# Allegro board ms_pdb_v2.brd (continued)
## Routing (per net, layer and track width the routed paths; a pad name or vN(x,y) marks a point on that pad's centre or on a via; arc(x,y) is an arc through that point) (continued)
T6_BLAD1_EN: length 112.2
  IN1 w0.127: J12.S3 83.46,235.78 v2(83.46,237.05) 83.46,239.82 84.26,240.62 84.26,241.45 83.46,242.25 83.46,245.37 64.11,264.73 18.13,264.73 12.02,270.84 7.96,270.84 6.95,271.86 3.65,271.86 3.06,272.44 3.06,274.56 J25.B76
T6_BLAD1_RXD: length 106.9
  IN1 w0.127: J25.B81 5.42,270.67 6.16,269.93 6.61,269.93 7.66,268.88 12.79,268.88 17.67,264 63.9,264 82.32,245.58 v2(82.32,240.31) 82.32,238.32 81.76,237.75 81.76,236.05 86.9,230.91 86.9,229.8 J12.S2
T6_BLAD1_TXD: length 106.2
  IN1 w0.127: J12.S1 85.64,231.69 81.37,235.96 81.37,241.43 v2(81.64,241.7) 81.64,245.79 63.79,263.64 17.53,263.64 12.62,268.55 7.52,268.55 6.47,269.59 5.74,269.59 5.66,269.67 J25.B82
T6_BLAD2_RXD: length 113.9
  IN2 w0.127: J12.S6 91.99,232.46 v2(87.29,237.17) 85.32,239.13 85.32,241.52 62.43,264.42 17.59,264.42 9.12,255.95 7.9,255.95 6.93,256.92 5.99,256.92 5.19,257.72 5.19,259.57 4.09,260.67 J26.B2
T6_BLAD2_TXD: length 109
  IN2 w0.127: J26.B3 4.83,258.79 4.83,257.57 5.84,256.56 6.79,256.56 7.76,255.59 9.28,255.59 17.74,264.05 62.32,264.05 84.98,241.4 84.98,238.47 v2(85.38,238.06) 90.72,232.73 J12.S5
T6_BLAD3_EN: length 112.1
  IN1 w0.127: J25.B78 2.65,272.97 2.65,272.3 3.49,271.47 6.79,271.47 7.8,270.45 11.94,270.45 17.99,264.4 63.97,264.4 82.97,245.4 v2(82.97,238.71) 82.97,235.64 87.31,231.29 87.31,230.75 88.17,229.89 88.17,228.53 J12.S10
T6_BLAD3_RXD: length 111.9
  IN2 w0.127: J26.B5 5.57,256.05 5.57,255.17 5.81,254.93 6.92,254.93 8.01,253.84 8.91,253.84 9.64,254.58 9.64,255.3 18.03,263.69 62.22,263.69 84.46,241.45 v2(84.46,239.71) 84.46,237.86 85.28,237.05 85.28,234.76 84.78,234.26 84.78,230.55 86.91,228.42 J12.S11
T6_BLAD3_TXD: length 111.5
  IN2 w0.127: J12.S12 84.12,230.05 84.12,234.79 82.99,235.91 82.99,237.44 83.8,238.26 v2(83.8,240.98) 83.8,241.64 62.08,263.36 18.17,263.36 10.11,255.29 10.11,254.53 9.06,253.48 7.86,253.48 6.75,254.59 5.64,254.59 5.2,255.02 5.2,255.51 4.04,256.67 J26.B6
T6_BLAD4_RXD: length 117.9
  IN2 w0.127: J12.S7 90.97,226.23 86.54,226.23 83.53,229.24 83.53,234.37 82.26,235.65 v2(82.26,236.21) 82.26,239.44 82.81,239.99 82.81,242.17 64.1,260.88 48.52,260.88 47.85,261.55 16.86,261.55 10.64,255.33 10.64,253.55 8.89,251.8 8.05,251.8 6.97,252.88 5.76,252.88 5.27,253.37 5.27,254.35 J26.B7
T6_BLAD4_TXD: length 123.4
  IN2 w0.127: J26.B8 4.09,254.67 4.9,253.86 4.9,253.22 5.61,252.51 6.81,252.51 7.89,251.43 9.05,251.43 11.01,253.4 11.01,255.15 17.06,261.2 47.66,261.2 48.35,260.5 64,260.5 80.91,243.59 v2(80.91,239.06) 80.91,236.01 82.96,233.96 82.96,229.24 86.37,225.83 91.81,225.83 92.87,226.89 92.87,227.77 92.5,228.14 91.1,228.14 J12.S8
T7_BLAD1_EN: length 212.6
  IN2 w0.127: J25.A65 5.38,285.6 5.38,284.38 5.94,283.81 7.25,283.81 7.92,284.48 22.29,284.48 28.3,290.49 28.3,349.46 30.11,351.27 43.29,351.27 45.75,348.81 61.53,348.81 80.59,329.74 80.59,323.51 83.5,320.6 83.5,314.67 91.71,306.45 91.71,298.17 84.86,291.31 84.86,282.71 v2(85.73,281.84) 88.18,279.39 J13.S3
T7_BLAD1_RXD: length 207.3
  IN2 w0.127: J13.S2 86.91,279 83.56,282.34 v2(83.56,284.76) 83.56,291.39 90.74,298.57 90.74,306.92 81.32,316.35 81.32,321.77 79.87,323.21 79.87,329.45 60.88,348.44 45.47,348.44 43.36,350.55 30.43,350.55 29.02,349.14 29.02,290.13 22.56,283.68 10.46,283.68 J25.A70
T7_BLAD1_TXD: length 207.5
  IN2 w0.127: J13.S1 85.64,279.41 82.95,282.11 v2(82.95,286.1) 82.95,291.34 90.34,298.73 90.34,306.76 80.92,316.18 80.92,321.6 79.47,323.05 79.47,329.28 60.67,348.08 45.25,348.08 43.18,350.15 30.52,350.15 29.42,349.05 29.42,290 22.71,283.29 11.11,283.29 8.48,280.67 J25.A71
T7_BLAD2_RXD: length 97.1
  IN1 w0.127: J13.S6 91.99,275.53 89.8,277.72 85.14,277.72 84.17,276.75 84.17,272.34 79.92,268.09 22.18,268.09 v2(21.02,269.25) 13.27,277 11.12,277 J25.A72
T7_BLAD2_TXD: length 96.1
  IN1 w0.127: J25.A73 8.72,276.4 12.42,276.4 21.29,267.53 v2(78.66,267.53) 79.85,267.53 84.58,272.26 84.58,276.58 85.24,277.24 89,277.24 J13.S5
T7_BLAD3_EN: length 212
  IN2 w0.127: J13.S10 88.18,274.25 89.04,275.11 89.04,279.49 v2(87.4,281.13) 85.19,283.34 85.19,291.16 92.05,298.03 92.05,306.59 83.84,314.81 83.84,320.74 80.93,323.65 80.93,329.89 61.66,349.15 46,349.15 43.54,351.61 29.97,351.61 27.96,349.6 27.96,290.77 22.01,284.83 7.51,284.83 7.35,284.67 J25.A67
T7_BLAD3_RXD: length 86.7
  IN1 w0.127: J13.S11 v2(82.36,267.15) 81.82,266.61 18.85,266.61 10.65,274.82 8.3,274.82 J25.A75
T7_BLAD3_TXD: length 83.6
  IN1 w0.127: J25.A76 12.61,275.67 21.33,266.94 80.13,266.94 v2(80.67,267.47) 85.64,272.45 J13.S12
T7_BLAD4_RXD: length 91.3
  IN1 w0.127: J25.A77 7.65,274.67 7.91,274.41 10.57,274.41 18.75,266.22 85.07,266.22 v2(85.26,266.42) 90.55,271.71 J13.S7
T7_BLAD4_TXD: length 93.3
  IN1 w0.127: J13.S8 92.08,272.98 92.86,272.2 92.86,271.24 v2(87.78,266.15) 87.52,265.89 18.61,265.89 10.83,273.67 J25.A78
T8_BLAD1_EN: length 162.9
  IN1 w0.127: J25.B61 2.97,289.69 2.97,288.32 3.32,287.97 4.14,287.97 6.22,285.89 7.09,285.89 8.02,286.82 8.71,286.82 8.94,287.05 21.61,287.05 27.58,293.02 27.58,349.15 29.65,351.22 44.71,351.22 47.35,348.58 60.04,348.58 82.48,326.14 v2(83.72,326.14) 88.18,321.68 J14.S3
T8_BLAD1_RXD: length 160.6
  IN1 w0.127: J25.B66 4.05,285.67 5.77,283.96 6.98,283.96 7.87,284.85 9.21,284.85 9.71,285.35 20.86,285.35 28.25,292.74 28.25,348.64 30.03,350.42 44.58,350.42 46.75,348.25 59.9,348.25 v2(83.17,324.98) 86.53,321.62 86.53,319.88 86.91,319.51 J14.S2
T8_BLAD1_TXD: length 155.9
  IN1 w0.127: J25.B67 5.1,283.52 7.27,283.52 8.25,284.5 9.39,284.5 9.89,285.01 21,285.01 28.59,292.6 28.59,348.37 30.21,349.98 44.55,349.98 46.61,347.92 59.51,347.92 v2(81.78,325.65) 85.64,321.79 J14.S1
T8_BLAD2_RXD: length 167.2
  IN2 w0.127: J25.B68 3.96,281.66 4.25,281.66 4.75,281.16 4.75,280.66 5.85,279.55 6.86,279.55 6.95,279.46 7.91,278.5 9.33,278.5 10.34,277.49 10.34,276.73 18.75,268.32 71.42,268.32 72.49,269.39 94.47,269.39 99.13,274.05 99.13,288.76 94.91,292.98 v2(94.91,304.79) 94.91,306.96 84.85,317.01 84.85,320.28 85.64,321.06 88.37,321.06 90.26,319.17 91.52,319.17 J14.S6
T8_BLAD2_TXD: length 163.1
  IN2 w0.127: J25.B69 5.15,281.47 5.15,280.83 6.02,279.96 6.93,279.96 8.05,278.84 9.55,278.84 10.8,277.58 10.8,276.83 18.92,268.71 70.95,268.71 72.11,269.87 94.49,269.87 98.8,274.19 98.8,288.48 94.37,292.91 v2(94.37,306) 94.37,306.79 84.52,316.63 84.52,320.44 85.48,321.39 89.29,321.39 J14.S5
T8_BLAD3_EN: length 162.6
  IN1 w0.127: J14.S10 88.18,318.82 89.01,319.65 89.01,321.74 v2(83.29,327.46) 81.62,327.46 60.11,348.97 47.43,348.97 44.85,351.55 29.51,351.55 27.25,349.29 27.25,293.16 21.62,287.54 10.47,287.54 9.57,288.43 8.09,288.43 7.25,287.59 6.05,287.59 4.96,288.67 J25.B63
T8_BLAD3_RXD: length 151.1
  IN2 w0.127: J14.S11 87.72,315.34 95.62,307.44 v2(95.62,303.53) 95.62,292.84 99.46,289.01 99.46,273.91 94.41,268.86 72.67,268.86 71.78,267.97 18.61,267.97 9.77,276.82 8.02,276.82 7.09,277.75 6.19,277.75 5.37,278.58 5.37,279.25 J25.B71
T8_BLAD3_TXD: length 155.9
  IN2 w0.127: J14.S12 86.87,317.43 96.35,307.95 v2(96.35,302.2) 96.35,292.58 99.79,289.14 99.79,273.77 94.49,268.47 74.03,268.47 73.12,267.56 18.44,267.56 9.52,276.48 7.88,276.48 6.94,277.41 6.05,277.41 5.03,278.44 5.03,278.78 4.14,279.67 J25.B72
T8_BLAD4_RXD: length 150.4
  IN2 w0.127: J14.S7 97.35,310.79 v2(97.35,300.77) 96.8,300.22 96.8,292.73 100.12,289.4 100.12,273.51 94.63,268.02 76.91,268.02 76.11,267.21 18.29,267.21 11.68,273.82 10.7,274.8 8.06,274.8 7.03,275.82 6.14,275.82 5.22,276.74 5.22,277.4 J25.B73
T8_BLAD4_TXD: length 155
  IN2 w0.127: J25.B74 4.09,277.67 4.89,276.86 4.89,276.6 6,275.49 6.89,275.49 8.01,274.38 10.56,274.38 18.06,266.88 80.83,266.88 81.1,266.61 83.09,266.61 83.36,266.88 94.04,266.88 100.45,273.29 100.45,289.62 98.25,291.82 v2(98.25,299.68) 98.25,311.38 92.21,317.43 J14.S8
T9_BLAD1_EN: length 128.9
  IN2 w0.127: J15.S3 86.85,364.42 84.52,362.09 84.52,361.32 80.44,357.23 45.74,357.23 44.22,358.75 39.65,358.75 38.04,357.14 27.23,357.14 v2(24.51,354.43) 22.28,352.2 22.28,350.57 21.89,350.18 21.89,315.24 9.98,303.33 9.98,303.2 J25.A50
T9_BLAD1_RXD: length 142.3
  IN2 w0.127: J15.S2 87.48,363.15 87.77,363.43 88.47,363.43 88.98,363.94 90.07,363.94 91.62,362.38 91.62,361.43 87.28,357.09 85.17,357.09 83.45,355.37 v2(82.71,355.37) 44.85,355.37 43.42,356.81 40.19,356.81 39.06,355.68 29.26,355.68 23.21,349.63 23.21,313.56 13.01,303.36 13.01,302.04 9.9,298.93 9.9,297.88 8.69,296.67 J25.A55
T9_BLAD1_TXD: length 147
  IN2 w0.127: J15.S1 86.79,365.57 90.95,365.57 92.89,363.63 92.89,360.23 89.08,356.41 ; 89.08,356.41 v2(89.08,356.42) ; 89.08,356.41 87.42,354.75 43.24,354.75 41.75,356.24 40.28,356.24 39.35,355.32 29.42,355.32 23.57,349.47 23.57,313.33 13.43,303.19 13.43,301.58 10.58,298.72 10.58,297.8 J25.A56
T9_BLAD2_RXD: length 156.9
  IN1 w0.127: J25.A57 9.58,294.67 13.9,290.35 20.44,290.35 23.07,292.98 23.07,349.62 28.04,354.6 39.4,354.6 39.72,354.91 39.74,354.91 v2(40.29,355.46) 42.95,358.12 82.91,358.12 84.54,359.74 84.54,365.12 85.28,365.86 90.71,365.86 91.99,364.58 J15.S6
T9_BLAD2_TXD: length 151.8
  IN1 w0.127: J25.A58 10.07,293.67 13.75,289.99 20.59,289.99 23.41,292.81 23.41,349.44 28.23,354.26 40.27,354.26 v2(41.67,355.66) 43.74,357.73 83,357.73 84.87,359.6 84.87,364.98 85.32,365.43 89.7,365.43 J15.S5
T9_BLAD3_EN: length 129.2
  IN2 w0.127: J15.S10 87.9,361.59 87.9,359.97 86.22,358.29 84.87,358.29 83.05,356.47 v2(79.8,356.47) 45.67,356.47 44.32,357.81 40.07,357.81 38.73,356.47 28.24,356.47 22.96,351.19 22.96,350.31 22.55,349.9 22.55,314.77 12.85,305.08 11.49,303.72 11.49,302.71 J25.A52
T9_BLAD3_RXD: length 142.2
  IN1 w0.127: J25.A60 9.71,291.67 12.13,289.24 20.9,289.24 24.07,292.41 24.07,349.06 28.56,353.55 42.09,353.55 42.78,354.24 v2(44.73,356.19) 45.45,356.91 83.22,356.91 J15.S11
T9_BLAD3_TXD: length 145.4
  IN1 w0.127: J25.A61 8.36,292.58 9.34,292.58 12.29,289.63 20.74,289.63 23.74,292.62 23.74,349.23 28.43,353.92 41.25,353.92 43.27,355.94 ; 43.27,355.94 v2(43.27,355.94) ; 43.27,355.94 44.7,357.38 83.11,357.38 85.64,359.91 J15.S12
T9_BLAD4_RXD: length 147.7
  IN1 w0.127: J25.A62 9.73,289.67 10.99,288.41 21.2,288.41 24.73,291.95 24.73,348.56 29.04,352.86 43.58,352.86 45.9,355.18 81.55,355.18 82.21,355.84 83.25,355.84 83.91,355.18 86.56,355.18 v2(87.41,356.02) J15.S7
T9_BLAD4_TXD: length 150.3
  IN1 w0.127: J25.A63 8.24,290.46 9.66,290.46 11.36,288.76 21.05,288.76 24.4,292.11 24.4,348.81 28.79,353.2 43.23,353.2 45.54,355.51 81.41,355.51 82.07,356.17 84.64,356.17 v2(85,355.8) 85.96,355.8 90.72,360.56 J15.S8
T10_BLAD1_EN: length 185.3
  IN1 w0.127: J16.S3 86.83,408.87 84.17,406.21 84.17,405.18 v2(79.27,400.27) 83.16,396.37 83.16,360.45 82.16,359.44 42.09,359.44 38.95,356.3 24.7,356.3 20.98,352.58 20.98,310.8 13,302.82 7.99,302.82 6.97,303.83 6.21,303.83 4.37,305.67 J25.B46
T10_BLAD1_RXD: length 184.4
  IN1 w0.127: J25.B51 4.86,299.76 6.92,299.76 7.76,298.92 11.24,298.92 22.41,310.09 22.41,350.27 27.4,355.27 38.85,355.27 42.36,358.78 82.43,358.78 83.83,360.17 83.83,398.24 v2(85.33,399.74) 90.3,404.71 90.3,405.56 89.89,405.97 89.89,406.74 90.46,407.31 90.46,407.89 89.93,408.43 89.1,408.43 88.74,408.06 87.37,408.06 J16.S2
T10_BLAD1_TXD: length 190.9
  IN1 w0.127: J16.S1 86.55,409.78 91.11,409.78 91.5,409.39 91.5,408.38 91.02,407.9 91.02,407.31 91.51,406.81 91.51,405.77 91.09,405.35 91.09,404.33 v2(84.7,397.94) 84.16,397.39 84.16,360.03 82.57,358.45 42.5,358.45 38.98,354.93 27.67,354.93 22.74,350 22.74,309.78 11.52,298.57 7.62,298.57 6.75,299.43 3.74,299.43 3.51,299.67 J25.B52
T10_BLAD2_RXD: length 227.6
  IN2 w0.127: J16.S6 91.99,408.8 90.24,410.55 85.05,410.55 83.9,409.41 83.9,402.63 v2(87.22,399.31) 99.08,387.45 99.08,358.59 94.87,354.38 28.98,354.38 23.98,349.38 23.98,293.02 21.47,290.52 13.53,290.52 9.14,294.91 7.92,294.91 7.04,295.79 6.28,295.79 3.95,298.12 J25.B53
T10_BLAD2_TXD: length 226.1
  IN2 w0.127: J25.B54 2.7,296.92 2.7,296.92 3,296.61 3,296.38 3.93,295.45 6.66,295.45 7.63,294.48 9.02,294.48 13.53,289.98 21.49,289.98 24.98,293.47 24.98,349.88 29.08,353.98 95,353.98 99.45,358.43 99.45,387.95 v2(88.57,398.83) 84.51,402.89 84.51,409.16 85.3,409.95 89.64,409.95 J16.S5
T10_BLAD3_EN: length 181
  IN1 w0.127: J16.S10 88.18,404.97 v2(82.22,399.01) 83.5,397.74 83.5,360.31 82.29,359.11 42.22,359.11 39.08,355.97 25.42,355.97 21.64,352.19 21.64,310.41 12.13,300.89 8.04,300.89 7.11,301.82 5.81,301.82 4.95,302.68 4.95,303.04 4.32,303.67 J25.B48
T10_BLAD3_RXD: length 215.8
  IN2 w0.127: J16.S11 86.91,402.38 v2(90.26,399.03) 100.2,389.09 100.2,358.12 95.34,353.26 29.56,353.26 26.48,350.17 26.48,292.84 22.44,288.8 12.61,288.8 8.82,292.6 7.97,292.6 7.2,293.37 4.25,293.37 J25.B56
T10_BLAD3_TXD: length 214.3
  IN2 w0.127: J25.B57 4.86,293.76 7.29,293.76 8.12,292.93 9.04,292.93 12.82,289.15 22.3,289.15 26.13,292.99 26.13,350.29 29.44,353.6 95.19,353.6 99.85,358.27 99.85,388.71 v2(88.45,400.11) 85.64,402.93 J16.S12
T10_BLAD4_RXD: length 216.2
  IN2 w0.127: J16.S7 91.99,399.23 v2(93.43,397.79) 100.97,390.25 100.97,357.8 95.66,352.48 29.81,352.48 27.25,349.93 27.25,291.21 23.36,287.31 12.27,287.31 9.16,290.42 7.98,290.42 6.95,291.46 4.16,291.46 J25.B58
T10_BLAD4_TXD: length 214.7
  IN2 w0.127: J16.S8 90.72,399.47 v2(91.7,398.5) 100.62,389.57 100.62,357.95 95.51,352.84 29.65,352.84 26.9,350.09 26.9,291.35 23.25,287.7 12.44,287.7 9.37,290.77 8.13,290.77 7.1,291.8 4.82,291.8 J25.B59
T11_BLAD1_EN: length 201.7
  IN2 w0.127: J17.S3 88.18,452.04 85.53,449.39 85.53,448.6 v2(82.25,445.32) 81.62,444.7 43.69,444.7 42.76,443.76 30.48,443.76 25.92,439.2 25.92,380.82 14.74,369.63 14.74,333.17 14.96,332.94 14.96,331.6 14.3,330.94 14.3,321.84 9.13,316.67 J25.A35
T11_BLAD1_RXD: length 206.9
  IN1 w0.127: J17.S2 86.91,450.81 87.82,449.9 87.82,449.21 86.97,448.36 86.48,448.36 82.46,444.33 44.45,444.33 v2(41.47,441.36) 40.41,440.3 30.64,440.3 27.84,437.49 27.84,379.62 19.66,371.45 19.66,314.38 16.95,311.67 J25.A40
T11_BLAD1_TXD: length 207
  IN1 w0.127: J25.A41 6.45,310.94 5.74,311.66 5.74,312.96 6.25,313.47 7.12,313.47 8.05,314.4 10.01,314.4 10.21,314.2 12.69,314.2 16.21,317.72 16.21,321.03 18.67,323.49 18.67,372.24 26.76,380.33 26.76,438.03 30.4,441.67 v2(36.8,441.67) 39.11,441.67 43.29,445.85 81.51,445.85 84.74,449.07 84.74,452.42 J17.S1
T11_BLAD2_RXD: length 210.3
  IN1 w0.127: J25.A42 15.5,309.67 19.99,314.16 19.99,371.23 28.22,379.46 28.22,437.33 30.86,439.97 40.92,439.97 v2(42.71,441.76) 44.94,443.98 83.51,443.98 88.34,448.82 88.34,449.58 90.81,452.05 J17.S6
T11_BLAD2_TXD: length 218.2
  IN1 w0.127: J25.A43 5.33,309.79 5.33,313.12 6.13,313.91 7.06,313.91 8.01,314.87 10.12,314.87 10.29,314.7 v2(12.56,314.7) 15.67,317.81 15.67,321.25 17.67,323.25 17.67,332.49 17.04,333.11 17.04,335.47 15.15,337.36 15.15,369.22 26.36,380.42 26.36,438.19 30.28,442.12 39.09,442.12 43.15,446.18 81.36,446.18 84.41,449.23 84.41,453.27 85.64,454.5 88.52,454.5 89.71,453.32 J17.S5
T11_BLAD3_EN: length 201.2
  IN2 w0.127: J25.A37 8.86,314.67 11.02,316.83 11.02,317.09 16.49,322.57 16.49,370.29 26.7,380.5 26.7,438.88 31.22,443.41 43.61,443.41 44.57,444.37 83.13,444.37 v2(83.79,445.03) 88.18,449.42 J17.S10
T11_BLAD3_RXD: length 208.9
  IN1 w0.127: J25.A45 6.94,306.67 7.58,307.3 7.58,311.88 8.14,312.45 15.82,312.45 19.33,315.96 19.33,371.6 27.47,379.73 27.47,437.59 30.63,440.75 v2(39.67,440.75) 39.92,440.75 43.95,444.78 82.41,444.78 86.91,449.28 J17.S11
T11_BLAD3_TXD: length 213
  IN1 w0.127: J17.S12 85.64,449.45 81.67,445.47 44.02,445.47 39.75,441.2 v2(38.18,441.2) 30.56,441.2 27.09,437.73 27.09,379.9 19,371.81 19,316.32 15.56,312.88 7.99,312.88 7.17,312.06 7.17,308.1 6.63,307.56 6.17,307.56 5.51,306.9 5.51,306.23 6.07,305.67 J25.A46
T11_BLAD4_RXD: length 213
  IN1 w0.127: J25.A47 11.29,304.67 20.32,313.7 20.32,371.07 28.6,379.35 28.6,437.22 30.94,439.57 41.52,439.57 v2(42.11,440.16) 45.6,443.65 86.13,443.65 J17.S7
T11_BLAD4_TXD: length 215.5
  IN1 w0.127: J25.A48 11.03,303.67 20.65,313.29 20.65,370.85 28.94,379.14 28.94,437.01 31.16,439.24 42.33,439.24 v2(44.04,440.96) 46.34,443.26 86.88,443.26 92.94,449.31 92.94,449.79 91.96,450.78 J17.S8
T12_BLAD1_EN: length 244
  IN1 w0.127: J18.S3 86.95,497.77 84.43,495.25 v2(84.43,489.4) 84.43,487.04 84.31,486.92 84.31,467.36 83.02,466.07 83.02,449.8 80.8,447.58 42.62,447.58 38.57,443.53 28.5,443.53 23.51,438.53 23.51,380.67 12.85,370.02 12.85,324.4 10.89,322.44 8.05,322.44 7.12,321.51 4.79,321.51 J25.B31
T12_BLAD1_RXD: length 253.2
  IN1 w0.127: J18.S2 88.14,496.5 89.12,497.48 89.75,497.48 90.42,496.82 90.42,496.09 89.94,495.62 89.94,494.76 90.28,494.42 90.28,489.32 v2(87.77,486.81) 84.97,484.01 84.97,467.09 83.69,465.8 83.69,449.54 81.07,446.92 42.9,446.92 38.75,442.78 29.62,442.78 24.92,438.08 24.92,380.03 14.3,369.41 14.3,324.58 12.76,323.04 12.76,320.92 8.59,316.75 7.86,316.75 7.05,315.94 4.49,315.94 4.23,315.67 J25.B36
T12_BLAD1_TXD: length 258.7
  IN1 w0.127: J18.S1 86.74,498.86 91.09,498.86 92.95,497 92.95,493.26 92.7,493.01 92.7,490.64 v2(87.48,485.43) 85.3,483.25 85.3,466.95 84.02,465.67 84.02,449.4 81.21,446.59 43.03,446.59 38.89,442.45 29.88,442.45 25.28,437.85 25.28,379.89 14.75,369.36 14.75,337.03 16.51,335.27 16.51,324.09 8.83,316.41 8.14,316.41 7.22,315.49 4.77,315.49 J25.B37
T12_BLAD2_RXD: length 281.7
  IN2 w0.127: J25.B38 2.18,313.9 7.12,313.9 8.15,312.87 12.34,312.87 19.91,320.44 19.91,351 20.23,351.32 20.23,372.96 27.45,380.18 27.45,438.57 31.83,442.95 44.13,442.95 45.22,444.04 89.17,444.04 98.52,453.38 98.52,481.91 93.93,486.5 92.37,486.5 v2(91.01,487.85) 84.29,494.57 84.29,498.14 85.36,499.21 90.63,499.21 91.99,497.85 J18.S6
T12_BLAD2_TXD: length 277.7
  IN2 w0.127: J18.S5 89.76,498.72 85.47,498.72 84.7,497.95 84.7,494.85 v2(92.29,487.25) 93.67,487.25 98.86,482.06 98.86,453.26 89.26,443.66 45.57,443.66 44.48,442.57 32.13,442.57 27.86,438.3 27.86,379.91 20.63,372.68 20.63,351.26 20.24,350.86 20.24,318.63 14.14,312.52 7.91,312.52 6.96,313.47 4.75,313.47 J25.B39
T12_BLAD3_EN: length 241.7
  IN1 w0.127: J18.S10 88.18,490.03 v2(86.45,488.29) 86.45,487.47 84.64,485.67 84.64,467.22 83.35,465.93 83.35,449.66 80.94,447.25 42.76,447.25 38.69,443.19 29.09,443.19 24.24,438.34 24.24,380.37 13.26,369.39 13.26,324.17 9.5,320.41 8.15,320.41 7.16,319.41 4.69,319.41 J25.B33
T12_BLAD3_RXD: length 267.1
  IN2 w0.127: J18.S11 v2(92.31,488.56) 92.86,488.56 99.21,482.21 99.21,453.04 89.49,443.32 45.94,443.32 44.86,442.23 32.44,442.23 28.21,438.01 28.21,379.62 20.96,372.37 20.96,351.12 20.57,350.73 20.57,318.24 13.17,310.84 8.11,310.84 7.12,311.84 5.12,311.84 J25.B41
T12_BLAD3_TXD: length 272.3
  IN2 w0.127: J18.S12 86.83,495.23 v2(93.92,488.14) 99.58,482.47 99.58,452.79 89.75,442.96 46.82,442.96 43.57,439.71 30.5,439.71 28.57,437.78 28.57,379.39 21.29,372.12 21.29,350.99 20.9,350.59 20.9,318.05 13.25,310.4 7.88,310.4 6.84,311.44 5.93,311.44 4.33,309.85 2.13,309.85 J25.B42
T12_BLAD4_RXD: length 268
  IN2 w0.127: J18.S7 91.99,491.36 v2(96.37,486.98) 100.29,483.07 100.29,452.34 90.17,442.23 47.07,442.23 43.89,439.05 31,439.05 29.28,437.33 29.28,377.79 21.95,370.47 21.95,350.71 21.56,350.32 21.56,316.46 13.51,308.42 8.06,308.42 7.27,307.63 4.99,307.63 J25.B43
T12_BLAD4_TXD: length 271.2
  IN2 w0.127: J18.S8 90.72,491.96 v2(95.19,487.49) 99.92,482.76 99.92,452.57 89.91,442.56 46.92,442.56 43.74,439.38 30.81,439.38 28.93,437.5 28.93,379.14 21.62,371.83 21.62,350.85 21.23,350.45 21.23,316.65 13.46,308.88 7.24,308.88 6.7,309.42 3.7,309.42 J25.B44
TP_T1_BLAD4_EN: length 5.2
  TOP w0.152: J26.A33 v1(11.63,227.67)
TP_T2_BLAD2_EN: length 10.7
  TOP w0.152: J26.B28 6.87,232.67 7.87,233.68 v1(12.21,233.68)
TP_T2_BLAD4_EN: length 10.1
  TOP w0.152: v1(11.68,231.63) 7.7,231.63 6.75,230.67 J26.B30
TP_T3_BLAD2_EN: length 4
  TOP w0.152: v1(12.15,243.86) 10.7,243.86 9.89,244.67 J26.A16
TP_T3_BLAD4_EN: length 5
  TOP w0.152: v1(13.2,242.11) 10.38,242.11 9.82,242.67 J26.A18
TP_T4_BLAD2_EN: length 9
  TOP w0.152: J26.B13 4.61,247.67 5.68,246.6 6.94,246.6 8.14,247.8 v1(11.97,247.8)
TP_T4_BLAD4_EN: length 9.8
  TOP w0.152: J26.B15 4.58,245.67 5.49,244.76 6.88,244.76 7.88,245.77 v1(12.99,245.77)
TP_T5_BLAD2_EN: length 3.6
  TOP w0.152: J25.A82 v1(12.06,269.67)
TP_T5_BLAD4_EN: length 5.8
  TOP w0.152: J26.A3 v1(12.24,259.67)
TP_T6_BLAD2_EN: length 9.3
  TOP w0.152: v1(12.15,275.75) 11.12,274.72 8,274.72 7.21,275.51 5.14,275.51 4.29,274.67 J25.B77
TP_T6_BLAD4_EN: length 9.1
  TOP w0.152: v1(12.11,273.23) 11.68,272.8 8.04,272.8 7.21,273.63 5.31,273.63 4.34,272.67 J25.B79
TP_T7_BLAD2_EN: length 3.8
  TOP w0.152: v1(11.96,284.9) 11.19,285.67 J25.A66
TP_T7_BLAD4_EN: length 3.8
  TOP w0.152: v1(12.04,283.1) 11.48,283.67 J25.A68
TP_T8_BLAD2_EN: length 10.5
  TOP w0.152: J25.B62 7.06,289.67 7.99,288.74 v1(12.08,288.74)
TP_T8_BLAD4_EN: length 10.3
  TOP w0.152: v1(11.94,286.83) 7.96,286.83 7.11,287.67 J25.B64
TP_T9_BLAD2_EN: length 7.4
  TOP w0.152: v1(11.64,305.4) 8.96,302.72 8.05,302.72 6.45,301.11 J25.A51
TP_T9_BLAD4_EN: length 7.7
  TOP w0.152: v1(11.83,303.49) 9.11,300.77 8,300.77 6.45,299.22 J25.A53
TP_T10_BLAD2_EN: length 9.5
  TOP w0.152: J25.B47 4.3,304.67 5.34,305.71 7.13,305.71 8.1,306.67 8.9,306.67 11.06,308.83 v1(11.77,308.83)
TP_T10_BLAD4_EN: length 10.5
  TOP w0.152: v1(12.66,307.01) 10.93,307.01 8.56,304.64 8.01,304.64 7.05,303.68 5.29,303.68 4.28,302.67 J25.B49
TP_T11_BLAD2_EN: length 3.2
  TOP w0.152: J25.A36 v1(11.61,315.67)
TP_T11_BLAD4_EN: length 3.7
  TOP w0.152: J25.A38 10.95,313.67 v1(11.79,312.83)
TP_T12_BLAD2_EN: length 13.7
  TOP w0.152: v1(13.88,316.16) 13.65,316.4 11.36,316.4 11.04,316.72 7.7,316.72 6.95,317.47 6.12,317.47 5.41,318.17 5.41,318.77 4.52,319.67 J25.B32
TP_T12_BLAD4_EN: length 14.1
  TOP w0.152: J25.B34 4.72,317.67 5.31,317.08 5.31,316.38 6.23,315.46 7.25,315.46 8.13,314.58 11.14,314.58 11.85,313.88 v1(14.1,313.88)
UART_CTS_P1_L_N: length 214.9
  IN1 w0.127: J26.B65 3.04,194.76 3.04,193.4 3.54,192.9 4.51,192.9 5.34,192.06 5.34,191.57 6.07,190.84 7.08,190.84 7.99,189.93 9.05,189.93 10.08,188.9 10.08,178.16 19.63,168.61 19.63,131.95 8.93,121.24 8.93,114.81 12.33,111.41 12.33,107.23 11.1,106.01 11.1,91.19 14.22,88.06 14.22,75.98 11.14,72.9 11.14,61.22 18.39,53.98 18.39,41.89 9.49,32.99 9.49,21.56 11.55,19.49 11.55,15.46 13.09,13.92 14.28,13.92 15.34,12.86 15.34,10.18 J19.8
UART_CTS_P2_L_N: length 176.5
  IN2 w0.127: J21.8 13.53,43.56 12.38,44.72 12.38,48.28 11.62,49.04 11.62,54.5 18.09,60.97 18.16,60.97 18.29,61.09 18.29,86.63 10.51,94.41 10.51,113.58 9.25,114.84 9.25,120.95 16.77,128.47 17.94,128.47 22.28,132.81 22.28,159.77 12.3,169.75 12.3,192.24 8.86,195.67 J26.A65
UART_CTS_P5_L_N: length 168.6
  IN2 w0.127: 16.5,62.1 17.84,63.44 17.84,67.92 17.16,68.6 15.82,68.6 14.67,67.45 13,67.45 11.4,69.04 11.4,73.5 10.18,74.72 10.18,90.42 8.36,92.24 6.21,92.24 4.45,94.01 4.45,111.86 7.93,115.34 7.93,121.5 16.22,129.79 17.2,129.79 20.36,132.96 20.36,159.82 11.79,168.39 10.9,169.28 10.9,190.25 9.57,191.58 7.91,191.58 7.02,192.47 5.84,192.47 4.71,193.6 4.71,202.91 J26.B57
UART_CTS_P6_L_N: length 124.8
  BOTTOM w0.152: J27.8 16.24,96.38 13.25,96.38 11.73,97.9 11.73,99.56 10.89,100.39 10.89,109.91 6.72,114.08 6.72,120.53 19.27,133.09 19.27,140.29 17.46,142.11 17.46,193.66 9.71,201.41 8.08,201.41 6.45,203.04 J26.A57
UART_DSR_P1_L_N: length 211.3
  IN1 w0.127: J26.B61 4.54,199.67 5.32,198.89 5.32,195.04 5.83,194.53 7.01,194.53 8.02,193.51 8.92,193.51 11.07,191.37 11.07,178.57 20.62,169.02 20.62,131.53 9.92,120.83 9.92,115.22 13.32,111.82 13.32,106.82 12.09,105.6 12.09,91.6 15.22,88.47 15.22,75.57 12.14,72.49 12.14,61.63 19.38,54.39 19.38,41.48 10.48,32.58 10.48,21.97 12.55,19.9 12.55,17.66 13.57,16.64 J19.2
UART_DSR_P2_L_N: length 172.8
  IN2 w0.127: J26.A61 8.49,199.67 13.69,194.46 13.69,173.45 23.7,163.43 23.7,132.08 18.77,127.15 17.31,127.15 10.57,120.4 10.57,115.53 11.93,114.17 11.93,95 19.71,87.22 19.71,60.5 18.75,59.54 18.68,59.54 13.03,53.9 13.03,51.78 13.62,51.18 J21.2
UART_DSR_P5_L_N: length 161.5
  IN2 w0.127: J23.2 13.19,69.72 12.11,70.8 12.11,73.79 10.89,75.01 10.89,90.72 8.65,92.95 6.5,92.95 5.16,94.3 5.16,111.56 8.59,115 8.59,121.23 16.49,129.13 17.63,129.13 21.07,132.57 21.07,160.04 11.61,169.5 11.61,191.17 9.23,193.54 8.03,193.54 7.15,194.42 6.13,194.42 5.38,195.16 5.38,206.24 J26.B53
UART_DSR_P6_L_N: length 122.3
  BOTTOM w0.152: J26.A53 6.45,208.16 7.84,209.56 8.79,209.56 9.62,208.73 9.62,206.64 10.28,205.98 10.28,203.98 19.59,194.67 19.59,143 21.41,141.18 21.41,132.2 8.85,119.65 8.85,115.67 15.26,109.26 15.26,105.51 J27.2
UART_DTR_P1_L_N: length 213
  IN1 w0.127: 13.96,10.29 13.96,11.21 11.22,13.95 11.22,19.36 9.16,21.42 9.16,33.13 18.06,42.03 18.06,53.84 10.81,61.08 10.81,73.04 13.89,76.12 13.89,87.92 10.77,91.05 10.77,106.15 11.99,107.37 11.99,111.27 8.6,114.67 8.6,121.38 19.3,132.08 19.3,168.47 9.72,178.05 9.72,188.77 8.97,189.53 7.83,189.53 6.92,190.44 5.91,190.44 4.95,191.4 4.95,191.9 4.34,192.5 3.37,192.5 2.71,193.17 2.71,195.91 J26.B64
UART_DTR_P2_L_N: length 171.2
  IN2 w0.127: J21.7 12.74,46.06 12.74,48.42 11.97,49.19 11.97,54.35 18.23,60.61 18.31,60.61 18.64,60.95 18.64,86.78 10.87,94.55 10.87,113.73 9.58,115.01 9.58,120.81 16.9,128.14 18.11,128.14 22.64,132.66 22.64,159.88 12.63,169.89 12.63,192.49 J26.A64
UART_DTR_P5_L_N: length 163.8
  IN2 w0.127: J26.B56 1.95,204.35 1.25,203.65 1.25,202.38 2.65,200.98 2.65,200.29 2.5,200.14 2.5,199.2 2.65,199.05 2.65,198.29 2.46,198.11 2.46,197.23 2.7,196.99 2.7,196.35 2.48,196.13 2.48,195.21 2.75,194.94 2.75,194.4 2.59,194.23 2.59,193.11 3.03,192.67 3.03,191.18 3.75,190.46 4.56,190.46 6.25,188.76 6.94,188.76 7.96,187.74 9.29,187.74 9.75,187.28 9.75,169.02 10.98,167.8 19.22,159.56 19.22,133.3 16.69,130.78 15.81,130.78 6.94,121.91 6.94,115.97 3.45,112.48 3.45,93.56 5.92,91.1 7.88,91.1 9.04,89.95 9.04,74.24 10.26,73.02 10.26,67.08 J23.7
UART_DTR_P6_L_N: length 121.1
  BOTTOM w0.152: J27.7 11.39,100.49 11.39,110.12 7.07,114.43 7.07,120.38 19.63,132.94 19.63,140.44 17.81,142.26 17.81,193.93 9.84,201.9 8.12,201.9 7.72,202.3 7.72,203.94 J26.A56
UART_RI_P5_L_N: length 163.6
  IN2 w0.127: J23.4 16.5,66.75 14.46,64.71 13.35,64.71 10.59,67.48 10.59,73.16 9.37,74.38 9.37,90.08 8.02,91.43 6.05,91.43 3.78,93.7 3.78,112.31 7.27,115.8 7.27,121.77 15.95,130.45 16.83,130.45 19.55,133.17 19.55,159.7 11.23,168.01 10.11,169.14 10.11,188 8.66,189.44 8.05,189.44 7.1,190.4 6.21,190.4 4.2,192.41 3.76,192.41 2.92,193.24 2.92,194.1 3.08,194.26 3.08,195.08 2.82,195.35 2.82,195.99 3.04,196.22 3.04,197.13 2.83,197.34 2.83,198.01 3.01,198.19 3.01,199.15 2.86,199.31 2.86,200.03 3.04,200.22 3.04,201.13 2.92,201.24 2.92,201.7 J26.B58
UART_RI_P6_L_N: length 125.3
  BOTTOM w0.152: J26.A58 9.58,202.67 18.17,194.08 18.17,142.41 19.99,140.59 19.99,132.79 7.43,120.24 7.43,114.61 11.77,110.27 11.77,100.76 13.34,99.19 14.74,99.19 15.98,97.94 17.1,97.94 17.56,98.41 17.56,100.75 16.58,101.73 J27.4
UART_RTS_P1_L_N: length 210.2
  IN1 w0.127: J26.B60 4.34,200.67 5.65,199.36 5.65,195.18 5.97,194.86 7.15,194.86 8.16,193.84 9.06,193.84 11.4,191.5 11.4,178.71 20.95,169.16 20.95,131.4 10.25,120.7 10.25,115.36 13.65,111.96 13.65,106.68 12.43,105.46 12.43,91.73 15.55,88.61 15.55,75.43 12.47,72.35 12.47,61.77 19.71,54.53 19.71,41.34 10.81,32.45 10.81,22.11 12.88,20.04 12.88,19 J19.1
UART_RTS_P2_L_N: length 167.5
  IN2 w0.127: J21.1 13.87,52.54 13.87,54.24 18.82,59.19 18.9,59.19 20.07,60.36 20.07,87.37 12.29,95.14 12.29,114.32 10.9,115.71 10.9,120.27 17.45,126.82 19.01,126.82 24.06,131.87 24.06,163.58 14.05,173.59 14.05,195.07 J26.A60
UART_RTS_P5_L_N: length 156.3
  IN2 w0.127: J23.1 12.47,72.49 12.47,73.94 11.25,75.16 11.25,90.86 10.08,92.03 10.08,113.1 8.92,114.26 8.92,121.09 16.63,128.8 17.77,128.8 21.43,132.46 21.43,160.15 11.97,169.62 11.97,191.31 9.38,193.9 8.18,193.9 7.3,194.77 6.27,194.77 5.74,195.31 5.74,207.13 4.2,208.67 J26.B52
UART_RTS_P6_L_N: length 116.5
  BOTTOM w0.152: J27.1 14.84,106.41 14.84,109.15 8.5,115.49 8.5,119.8 21.05,132.35 21.05,141.03 19.23,142.85 19.23,194.52 9.92,203.84 9.92,205.76 9.25,206.43 9.25,207.87 J26.A52
UART_RX_P1_L: length 210.7
  IN1 w0.127: J26.B62 4.45,198.67 4.99,198.13 4.99,193.91 6.13,192.77 7.09,192.77 7.91,191.95 8.88,191.95 10.74,190.09 10.74,178.43 20.29,168.88 20.29,131.67 9.59,120.97 9.59,115.08 12.99,111.68 12.99,106.96 11.76,105.74 11.76,91.46 14.88,88.34 14.88,75.71 11.8,72.63 11.8,61.5 19.05,54.25 19.05,41.62 10.15,32.72 10.15,21.83 12.22,19.77 12.22,17.12 J19.3
UART_RX_P2_L: length 168.3
  IN2 w0.127: J21.3 12.68,51.2 12.68,54.05 18.53,59.9 18.6,59.9 19.36,60.65 19.36,87.07 11.58,94.85 11.58,114.02 10.24,115.36 10.24,120.54 17.18,127.48 18.63,127.48 23.35,132.2 23.35,160.1 13.34,170.11 13.34,193.78 J26.A62
UART_RX_P5_L: length 161.2
  IN2 w0.127: J26.B54 4.09,206.67 5.05,205.72 5.05,193.77 5.99,192.83 7.17,192.83 8.06,191.94 9.71,191.94 11.25,190.39 11.25,169.39 20.72,159.93 20.72,132.81 17.37,129.46 16.36,129.46 8.26,121.36 8.26,115.17 4.8,111.71 4.8,94.15 6.36,92.6 8.51,92.6 10.54,90.57 10.54,74.87 11.76,73.64 11.76,70.66 J23.3
UART_RX_P6_L: length 117.4
  BOTTOM w0.152: J27.3 13.36,103 12.53,103.83 12.53,107.15 13.39,108.01 13.39,109.95 8.14,115.2 8.14,119.94 20.7,132.5 20.7,140.88 18.88,142.7 18.88,194.37 9.56,203.69 9.56,205.55 9.13,205.98 9.13,205.99 J26.A54
UART_TX_P1_L: length 217
  IN1 w0.127: J19.6 17.74,12.79 17.74,14.85 17.23,15.35 15.71,15.35 14.74,14.38 13.16,14.38 11.89,15.65 11.89,19.63 9.82,21.7 9.82,32.86 18.72,41.76 18.72,54.11 11.47,61.36 11.47,72.76 14.55,75.84 14.55,88.2 11.43,91.32 11.43,105.87 12.66,107.1 12.66,111.55 9.26,114.94 9.26,121.11 19.96,131.81 19.96,168.75 10.41,178.3 10.41,189.95 8.74,191.62 7.78,191.62 6.95,192.44 5.99,192.44 4.66,193.77 4.66,196.96 J26.B63
UART_TX_P2_L: length 175.1
  IN2 w0.127: J26.A63 8.92,197.67 12.98,193.6 12.98,170 22.99,159.99 22.99,132.41 18.39,127.81 17.04,127.81 9.91,120.68 9.91,115.19 11.22,113.88 11.22,94.7 19,86.92 19,60.8 18.46,60.25 18.38,60.25 12.33,54.2 12.33,49.34 12.99,48.67 14.24,48.67 16.5,46.4 J21.6
UART_TX_P5_L: length 168.7
  IN2 w0.127: J26.B55 3.25,204.97 3.25,201.38 3.38,201.25 3.38,200.09 3.25,199.96 3.25,199.38 3.38,199.26 3.38,198.09 3.25,197.96 3.25,197.38 3.4,197.23 3.4,196.11 3.19,195.9 3.19,195.44 3.41,195.22 3.41,194.12 3.25,193.96 3.25,193.38 3.82,192.81 4.32,192.81 6.33,190.81 7.27,190.81 8.22,189.85 9.6,189.85 10.52,188.93 10.52,169.19 11.52,168.19 19.9,159.81 19.9,133.02 17,130.12 16.08,130.12 7.6,121.64 7.6,115.55 4.11,112.07 4.11,93.84 6.09,91.86 8.2,91.86 9.8,90.26 9.8,74.56 11.02,73.34 11.02,68.61 12.58,67.05 14.96,67.05 16.11,68.2 16.78,68.2 17.41,67.57 17.41,65.55 J23.6
UART_TX_P6_L: length 123.8
  BOTTOM w0.152: J26.A55 8.66,205.67 9.2,205.13 9.2,203.54 18.52,194.23 18.52,142.55 20.34,140.74 20.34,132.65 7.78,120.09 7.78,115.02 13.01,109.8 13.01,108.16 12.15,107.3 12.15,102.85 13.06,101.94 14.36,101.94 16.5,99.8 J27.6
N42126673: length 5.9
  TOP w0.152: J29.10 2.46,141.33 2.46,143.61 2.77,143.92 R148.1
N42126764: length 3.1
  TOP w0.152: J29.9 4.06,143.18 R149.1
N42130542: length 2.7
  TOP w0.152: R150.2 3.41,129.94 J29.12
N42132358: length 2.8
  TOP w0.152: J28.12 3.73,398.67 R153.2
N42132545: length 6.1
  TOP w0.152: R151.1 2.68,414.45 2.68,409.84 J28.10
N42132933: length 3.4
  TOP w0.152: R152.1 4.2,412.06 J28.9
N42241895: length 4.3
  TOP w0.152: U2.1 17.88,453.08 16.79,454.17 v1(16.35,454.17) 15.91,453.73 R154.2
N42242090: length 9.7
  TOP w0.152: U2.4 21.69,451.76 22.33,451.11 23.09,451.11 v1(23.37,450.82) 23.82,450.37 23.82,446.67 22.9,445.75 R157.1 R156.2
N42242336: length 4
  TOP w0.152: C88.1 19.7,444.05 v1(19.1,444.65) 19.1,445.23 19.61,445.75 R155.2
N42263600: length 10.3
  TOP w0.152: R161.1 23.66,178.28 v1(23.66,179.41) 23.11,179.96 C92.1 22.19,179.51 21.47,178.79 R159.1 R158.2 19.77,177.58 19.77,175.89 19.31,175.44 U3.1
N42264085: length 7.4
  TOP w0.152: U3.8 v1(25.55,175.44) 25.55,176.04 25.2,176.39 23.1,176.39 22.52,176.97 R160.1 R159.2

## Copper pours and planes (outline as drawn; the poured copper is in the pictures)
GND on TOP (solid shape): outline of 271 points within 73,425.15 83,435.15
GND on TOP (solid shape): outline of 271 points within 73,336.25 83,346.25
GND on TOP (solid shape): outline of 271 points within 73,205.1 83,215.1
GND on TOP (solid shape): outline of 271 points within 73,116.2 83,126.2
GND on TOP (solid shape): outline of 271 points within 73,27.3 83,37.3
GND on TOP (solid shape): outline of 271 points within 73,514.05 83,524.05
GND on TOP (solid shape): outline of 272 points within 11.6,468.7 21.6,478.7
GND on TOP (solid shape): outline of 272 points within 11.6,379.8 21.6,389.8
GND on TOP (solid shape): outline of 272 points within 11.6,290.9 21.6,300.9
GND on TOP (solid shape): outline of 272 points within 11.6,202 21.6,212
GND on TOP (solid shape): outline of 272 points within 11.6,113.1 21.6,123.1
GND on TOP (solid shape): outline of 272 points within 11.6,24.2 21.6,34.2
GND on TOP (solid shape): outline of 335 points within 0.51,0.51 102.49,529.49
GND on BOTTOM (solid shape): 28.8,116.69 28.96,116.92 29.24,116.87 29.47,116.63 37.22,116.63 38.31,115.54 38.36,115.26 38.13,115.11 29.66,115.11 28.8,115.97
GND on BOTTOM (solid shape): outline of 271 points within 73,425.15 83,435.15
GND on BOTTOM (solid shape): outline of 271 points within 73,336.25 83,346.25
GND on BOTTOM (solid shape): outline of 271 points within 73,205.1 83,215.1
GND on BOTTOM (solid shape): outline of 271 points within 73,116.2 83,126.2
GND on BOTTOM (solid shape): outline of 271 points within 73,27.3 83,37.3
GND on BOTTOM (solid shape): outline of 271 points within 73,514.05 83,524.05
GND on BOTTOM (solid shape): outline of 272 points within 11.6,468.7 21.6,478.7
GND on BOTTOM (solid shape): outline of 272 points within 11.6,379.8 21.6,389.8
GND on BOTTOM (solid shape): outline of 272 points within 11.6,290.9 21.6,300.9
GND on BOTTOM (solid shape): outline of 272 points within 11.6,202 21.6,212
GND on BOTTOM (solid shape): outline of 272 points within 11.6,113.1 21.6,123.1
GND on BOTTOM (solid shape): outline of 272 points within 11.6,24.2 21.6,34.2
GND on BOTTOM (solid shape): outline of 335 points within 0.51,0.51 102.49,529.49
GND on BOTTOM (solid shape): outline of 12288 points within 1.53,132.45 24.05,378.91
GND on BOTTOM (solid shape): outline of 78036 points within 1.53,1.53 101.48,528.47
GND on GND (solid shape): outline of 8173 points within 0.51,0.51 102.49,529.49
GND on IN1 (solid shape): outline of 335 points within 0.51,0.51 102.49,529.49
GND on IN2 (solid shape): outline of 237 points within 8.85,313.19 19.91,372.9
GND on IN2 (solid shape): outline of 339 points within 0.51,0.51 102.49,529.49
GND on IN2 (solid shape): outline of 1953 points within 44.24,242.29 101.48,357.49
GND on IN2 (solid shape): outline of 13007 points within 8.74,269.03 98.48,349.83
GND on IN2 (solid shape): outline of 16487 points within 1.53,1.53 101.48,190.82
GND on IN2 (solid shape): outline of 25755 points within 1.53,53.4 101.48,260.88
GND on IN2 (solid shape): outline of 31785 points within 1.53,314.22 101.48,528.47
GND on GND1 (solid shape): outline of 8173 points within 0.51,0.51 102.49,529.49
P3V3_BUF on TOP (solid shape): 21.24,451.03 21.24,450.55 21.42,450.37 21.42,449.99 21.42,449.98 21.4,449.86 21.42,449.74 21.42,449.73 21.42,447.37 21.43,447.37 21.43,447.29 21.5,447.29 21.86,446.93 21.86,446.29 21.73,446.16 19.33,446.16 18.95,446.54 18.95,449.45 19.68,450.19 19.88,450.51 19.89,450.88 19.94,451.1 20.14,451.19 21.08,451.19
P12V on TOP (solid shape): 14.57,328.08 21.46,328.08 21.94,327.6 21.94,320.26 19.48,317.8 15.27,317.8 15.15,317.92 15.15,318.72 14.94,318.93 13.68,318.93 13.52,319.08 13.52,327.76 13.84,328.08 14.57,328.08
P12V on TOP (solid shape): outline of 2303 points within 1.27,180.27 21.17,202.84
P12V on TOP (solid shape): outline of 5527 points within 1.27,5.27 29.01,180.08
P12V on TOP (solid shape): outline of 81720 points within 1.27,2.43 101.73,528.73
P12V on IN1 (solid shape): outline of 90039 points within 1.27,1.5 101.73,528.73
P12V on VCC (solid shape): outline of 10290 points within 1.02,1.02 101.98,528.98
P12V on VCC1 (solid shape): outline of 10288 points within 1.02,1.02 101.98,528.98

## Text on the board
User.Comments: TEL:(03)327-2345 FAX:(03)397-3614 | PROJECT: | P/N: | DATE: | REV: | NO.188,WEN HWA 2ND RD. | KUEI SHAN HSIANG,TAO YUAN | SHIEN,TAIWAN R.O.C. | Layer | Tina | DAT6MTB88A0 | 2013/12/30 | T6MG_PDB_A_BD | A | 16 | Quanta
Ref Des/Silkscreen Top: Rev A | X892257-001 | P/N:DAT6MTB88A0 | Rev:A | REV LABEL | SW2 | SW3 | SW1 | COM2 | COM5 | TRAY BP 1 | TRAY BP 11 | TRAY BP 10 | TRAY BP 12 | TRAY BP 2 | TRAY BP 9 | TRAY BP 5 | TRAY BP 7 | TRAY BP 4 | TRAY BP 8 | TRAY BP 6 | TRAY BP 3 | RM_PWR | CM CONN 1 AND 2 | COM6 | FAN | LAN1 | COM1 | LAN2 | CONN | CM_PWR_CTL | PSU3 | PSU1 | PSU2 | PSU6 | PSU4 | PSU5
BODY_CENTER: 473.7 | 384.8 | 295.9 | 118.1 | 21.2 | 530 | 207 | 0 | 77 | 32.3 | 0.1 | 5.2 | ` | n | (12X) | 4 | 483.5 | 482.5 | 210.1 | 121.2 | 519.05 | 430.15 | 341.25 | 17 | 55 | 72 | 2.6 | R
DISPLAY_BOTTOM: (12X) | 4B | (6X) | 16 | 3B | 3I | n | 10 | 3E | 4A | NOTE: (UNLESS OTHERWISE SPECIFIED): | ==================================== | 1.MATERIAL: 2.4+/-0.1 MM THICK , NEMA GRADE FR-4 , | 2.COMPONENTS DIMENSIONED TO PIN 1. | 3.INDICATED AREA SHALL BE: | A- COPPER FREE | B- COMPONENT FREE | C- CONDUCTOR FREE | D- THROUGH HOLE COMPONENT FREE. | E- COPPER PAD COVERED WITH SOLID SOLDER | MASK CONNECTED TO GROUND , (GROUND PAD)(W/VIA) | F- COPPER PAD COVERED WITH SOLID SOLDER | MASK CONNECTED TO GROUND , (GROUND PAD) | G- COMPONENT FREE, EXCEPT FOR INDICATED CONN. | H- VIA FREE. | I- TRACE FREE | 4. COMPONENT HEIGHT IN THIS AREA SHALL BE: | A- 0MM MAX. | B- 15.49MM MAX. | C- 1.0MM MAX. | D- 9.91MM MAX. | E- 12.8MM MAX. | F- 7.98MM MAX. | G- 10.4MM MAX | H- 11.0MM MAX | 5. DRAWING FOR ECAD DESINGER REFERENCE ONLY . | ECAD LAYOUT SHALL MATCH LATEST PRO-E IDF | FILE
User.5: 521.05 | 503.05 | 444.35 | 414.15 | 355.45 | 325.25 | 266.55 | 236.35 | 177.65 | 147.45 | 488.8 | 458.6 | 399.9 | 369.7 | 280.8 | 222.1 | 191.9 | 133.2 | 88.75 | 58.55 | 44.3 | 14.1 | 530 | 311 | 103 | 0 | 25 | 47 | 72
User.6: 4A | 4B | (6X) | (12X) | 10 | 3B | 3E | 3I | n | 16 | 4D | 4F | 4H | 4E | (3X) | (2X) | (20X) | 4G | 4C
User.7: 473.7 | 384.8 | 295.9 | 118.1 | 21.2 | 530 | 207 | 0 | 77 | 32.3 | 0.1 | 5.2 | ` | n | (12X) | 4 | 483.5 | 482.5 | 210.1 | 121.2 | 519.05 | 430.15 | 341.25 | 17 | 55 | 72 | 2.6 | R
User.8: 521.05 | 503.05 | 444.35 | 414.15 | 355.45 | 325.25 | 266.55 | 236.35 | 177.65 | 147.45 | 488.8 | 458.6 | 399.9 | 369.7 | 280.8 | 222.1 | 191.9 | 133.2 | 88.75 | 58.55 | 44.3 | 14.1 | 530 | 311 | 103 | 0 | 25 | 47 | 72
User.9: 6 | 473.7 | 118.1 | 29.2 | 530 | 207 | 0 | 78.3 | 32.3 | 478.8 | 477.8 | 210.1 | 121.2 | 519.05 | 430.15 | 341.25 | 2.4 | 17.6 | 94 | 107 | D | E | F | G | H | 1 | 2 | 3 | 4 | 5
User.10: 530 | 0 | 306 | 108 | 39.3 | 19.1 | 520.8 | 510.8 | 483.8 | 463.6 | 394.9 | 374.7 | 285.8 | 217.1 | 196.9 | 128.2 | 83.75 | 63.55 | 439.35 | 419.15 | 350.45 | 330.25 | 261.55 | 241.35 | 172.65 | 152.45 | 43 | 84 | 107
User.11: 6 | 473.7 | 384.8 | 295.9 | 118.1 | 29.2 | 530 | 207 | 0 | 78.3 | 32.3 | 478.8 | 477.8 | 210.1 | 121.2 | 519.05 | 430.15 | 341.25 | (12X) | 4 | n | 0.1 | 5.2 | ` | 2.4 | 17.6 | 94 | 107 | 2.6 | R | A | B | C | D | E | F | G | H | 1 | 2 | 3 | 5
User.12: 530 | 0 | 306 | 108 | 39.3 | 19.1 | 520.8 | 510.8 | 483.8 | 463.6 | 394.9 | 374.7 | 285.8 | 217.1 | 196.9 | 128.2 | 83.75 | 63.55 | 439.35 | 419.15 | 350.45 | 330.25 | 261.55 | 241.35 | 172.65 | 152.45 | 43.8 | 84.8 | 107
User.13: 6 | 473.7 | 384.8 | 295.9 | 118.1 | 29.2 | 530 | 207 | 0 | (12X) | 4 | n | 0.1 | 5.2 | ` | 78.3 | 32.3 | 478.8 | 477.8 | 210.1 | 121.2 | 519.05 | 430.15 | 341.25 | 2.4 | 17.6 | 94 | 107 | 2.6 | R | A | B | C | D | E | F | G | H | 1 | 2 | 3 | 5
User.14: 530 | 0 | 107
User.15: 6 | 473.7 | 384.8 | 295.9 | 118.1 | 29.2 | 530 | 207 | 0 | (12X) | 4 | n | 0.1 | 5.2 | ` | 78.3 | 32.3 | 478.8 | 477.8 | 210.1 | 121.2 | 519.05 | 430.15 | 341.25 | 2.4 | 17.6 | 94 | 107 | 2.6 | R | A | B | C | D | E | F | G | H | 1 | 2 | 3 | 5
User.16: 530 | 0 | 107
User.17: 6 | 473.7 | 384.8 | 295.9 | 118.1 | 29.2 | 530 | 207 | 0 | (18X) | 10 | n | (12X) | 4 | 0.1 | 5.2 | ` | 78.3 | 32.3 | 478.8 | 477.8 | 121.2 | 519.05 | 210.1 | 430.15 | 341.25 | 2.4 | 5 | R | 20 | 17.6 | 94 | 107 | 2.6 | A | B | C | D | E | F | G | H | 1 | 2 | 3
User.18: 0 | 530 | 107
User.19: NOTE: (UNLESS OTHERWISE SPECIFIED): | ==================================== | 1.MATERIAL: 2.4+/-.1 MM THICK , NEMA GRADE FR-4 , | 2.COMPONENTS DIMENSIONED TO PIN 1. | 3.INDICATED AREA SHALL BE: | A- COPPER FREE | B- COMPONENT FREE | C- CONDUCTOR FREE | D- THROUGH HOLE COMPONENT FREE. | E- COPPER PAD COVERED WITH SOLID SOLDER | MASK CONNECTED TO GROUND , (GROUND PAD)(W/VIA) | F- COPPER PAD COVERED WITH SOLID SOLDER | MASK CONNECTED TO GROUND , (GROUND PAD) | G- COMPONENT FREE, EXCEPT FOR INDICATED CONN. | H- VIA FREE. | I- TRACE FREE | 5. DRAWING FOR ECAD DESINGER REFERENCE ONLY . | ECAD LAYOUT SHALL MATCH LATEST PRO-E IDF | FILE | 6 | 473.7 | 384.8 | 295.9 | 118.1 | 29.2 | 530 | 207 | 0 | (6X) | 10 | 3B | 3E | 3I | n | (12X) | 4 | 0.1 | 5.2 | ` | 78.3 | 32.3 | 478.8 | 477.8 | 121.2 | 519.05 | 210.1 | 430.15 | 341.25 | 2.4 | 5 | R | 20 | 17.6 | 94 | 107 | 2.6 | A | B | C | D | E | F | G | H | 1 | 2 | 3
User.20: 0 | 530 | (12X) | 10 | 3B | 3E | 3I | n | 107
User.22: NOTE: (UNLESS OTHERWISE SPECIFIED): | ==================================== | 1.MATERIAL: 2.4+/-.1 MM THICK , NEMA GRADE FR-4 , | 2.COMPONENTS DIMENSIONED TO PIN 1. | 3.INDICATED AREA SHALL BE: | A- COPPER FREE | B- COMPONENT FREE | C- CONDUCTOR FREE | D- THROUGH HOLE COMPONENT FREE. | E- COPPER PAD COVERED WITH SOLID SOLDER | MASK CONNECTED TO GROUND , (GROUND PAD)(W/VIA) | F- COPPER PAD COVERED WITH SOLID SOLDER | MASK CONNECTED TO GROUND , (GROUND PAD) | G- COMPONENT FREE, EXCEPT FOR INDICATED CONN. | H- VIA FREE. | I- TRACE FREE | 5. DRAWING FOR ECAD DESINGER REFERENCE ONLY . | ECAD LAYOUT SHALL MATCH LATEST PRO-E IDF | FILE | (6X) | 10 | 3E | 3I | 3b | n | 473.7 | 384.8 | 118.1 | 295.9 | 29.2 | 207 | 0 | 2.4 | (12X) | 8 | 508.96 | 464.51 | 420.06 | 375.61 | 331.16 | 286.71 | 242.26 | 197.81 | 153.36 | 108.91 | 20.01 | 64.46 | 530 | 4 | 526 | 3B | 16.6 | 103 | 91.4 | 2.6 | R | A | B | C | D | E | F | G | H | 1 | LTR | DESCRIPTION | REVISIONS | DATE | APP.
User.23: DWG NAME | T6M-PDB-ASSY | NOTE: (UNLESS OTHERWISE SPECIFIED): | ==================================== | 1.MATERIAL: 2.4+/-.1 MM THICK , NEMA GRADE FR-4 , | 2.COMPONENTS DIMENSIONED TO PIN 1. | 3.INDICATED AREA SHALL BE: | A- COPPER FREE | B- COMPONENT FREE | C- CONDUCTOR FREE | D- THROUGH HOLE COMPONENT FREE. | E- COPPER PAD COVERED WITH SOLID SOLDER | MASK CONNECTED TO GROUND , (GROUND PAD)(W/VIA) | F- COPPER PAD COVERED WITH SOLID SOLDER | MASK CONNECTED TO GROUND , (GROUND PAD) | G- COMPONENT FREE, EXCEPT FOR INDICATED CONN. | H- VIA FREE. | I- TRACE FREE | 5. DRAWING FOR ECAD DESINGER REFERENCE ONLY . | ECAD LAYOUT SHALL MATCH LATEST PRO-E IDF | FILE | 6 | (6X) | 10 | 3E | 3I | 3b | n | 473.7 | 384.8 | 118.1 | 295.9 | 29.2 | 207 | 0 | (12X) | 4 | 0.1 | 5.2 | ` | 3B | 78.3 | 32.3 | 478.8 | 477.8 | 121.2 | 519.05 | 210.1 | 430.15 | 341.25 | 2.4 | 8 | 508.96 | 464.51 | 420.06 | 375.61 | 331.16 | 286.71 | 242.26 | 197.81 | 153.36 | 108.91 | 20.01 | 64.46 | 530 | 526 | RANGE | 0-10 | 10-50 | 50-100 | 100- | TOLERENCE | 0.10 | 0.15 | 0.20 | 0.25 | TOL. | 1 | ITEM | NAME | MATERIAL | FINISH | SEE NOTE | TBD | PART NO. | L06 PDB ASSY | UNIT | SCALE | DATE | DWG NO. | MODEL | mm | 1:1 | 30-Mar-12 | DESCRIPTION | APPROVED | DESIGNED | DRAWN | REV. | 2 | JERRY | ALLEN | 1G | / | 3 | The 3D Projection | 16.6 | 78 | 103 | 91.4 | 2.6 | R | 1 PLC | 2 PLC | 3 PLC | L06 | 5 | A | B | C | D | E | F | G | H | LTR | Quanta Computer Inc. | REVISIONS | APP.
User.24: NOTE: (UNLESS OTHERWISE SPECIFIED): | ==================================== | 1.MATERIAL: 2.4+/-.1 MM THICK , NEMA GRADE FR-4 , | 2.COMPONENTS DIMENSIONED TO PIN 1. | 3.INDICATED AREA SHALL BE: | A- COPPER FREE | B- COMPONENT FREE | C- CONDUCTOR FREE | D- THROUGH HOLE COMPONENT FREE. | E- COPPER PAD COVERED WITH SOLID SOLDER | MASK CONNECTED TO GROUND , (GROUND PAD)(W/VIA) | F- COPPER PAD COVERED WITH SOLID SOLDER | MASK CONNECTED TO GROUND , (GROUND PAD) | G- COMPONENT FREE, EXCEPT FOR INDICATED CONN. | H- VIA FREE. | I- TRACE FREE | 5. DRAWING FOR ECAD DESINGER REFERENCE ONLY . | ECAD LAYOUT SHALL MATCH LATEST PRO-E IDF | FILE | 6 | (6X) | 10 | 3E | 3I | 3b | n | 473.7 | 384.8 | 118.1 | 295.9 | 526 | 29.2 | 207 | 4 | 0 | (12X) | 530 | 78.3 | 0.1 | 5.2 | ` | 32.3 | 519.05 | 478.8 | 477.8 | 121.2 | 210.1 | 430.15 | 341.25 | 3B | 2.4 | 508.96 | 464.51 | 420.06 | 375.61 | 331.16 | 286.71 | 242.26 | 197.81 | 153.36 | 108.91 | 8 | 20.01 | 64.46 | 16.6 | 25 | 78 | 103 | 91.4 | 2.6 | R | 1 | A | B | C | D | E | F | G | H | 2 | 3 | 5
User.25: NOTE: (UNLESS OTHERWISE SPECIFIED): | ==================================== | 1.MATERIAL: 2.4+/-.1 MM THICK , NEMA GRADE FR-4 , | 2.COMPONENTS DIMENSIONED TO PIN 1. | 3.INDICATED AREA SHALL BE: | A- COPPER FREE | B- COMPONENT FREE | C- CONDUCTOR FREE | D- THROUGH HOLE COMPONENT FREE. | E- COPPER PAD COVERED WITH SOLID SOLDER | MASK CONNECTED TO GROUND , (GROUND PAD)(W/VIA) | F- COPPER PAD COVERED WITH SOLID SOLDER | MASK CONNECTED TO GROUND , (GROUND PAD) | G- COMPONENT FREE, EXCEPT FOR INDICATED CONN. | H- VIA FREE. | I- TRACE FREE | 5. DRAWING FOR ECAD DESINGER REFERENCE ONLY . | ECAD LAYOUT SHALL MATCH LATEST PRO-E IDF | FILE | 6 | 384.8 | 295.9 | (6X) | 10 | 3E | 3I | 3b | n | 473.7 | 207 | 118.1 | 526 | 29.2 | 0 | 4 | 121.2 | 78.3 | 32.3 | (12X) | 530 | 210.1 | 430.15 | 341.25 | 0.1 | 5.2 | ` | 478.8 | 477.8 | 519.05 | 3B | 2.4 | 508.96 | 464.51 | 420.06 | 375.61 | 331.16 | 286.71 | 242.26 | 197.81 | 153.36 | 108.91 | 20.01 | 64.46 | 8 | 16.6 | 25 | 78 | 103 | 91.4 | 2.6 | R | A | B | C | D | E | F | G | H | 1 | 2 | 3 | 5
User.28: 0.25 TYP | 0.00 | 0.22 TYP | 0.55 TYP | 1.20 TYP | 20.68 | 20.36 | 19.61 | 18.79 | 18.18 | 17.20 | 16.13 | 13.88 | 13.72 | 10.30 | 10.24 | 6.76 | 5.55 | 4.16 | 3.40 | 3.28 | 2.80 | 2.07 | 1.26 | 0.71
User.29: 0.00 | 1.73 TYP | 19.58 | 17.83 | 16.08 | 14.33 | 12.58 | 10.83 | 9.08 | 7.33 | 5.58 | 3.83 | 2.08 | 0.33
User.30: TOP | 1
User.31: BOTTOM | 8
User.32: SILK-TOP
User.33: SILK-BOT
User.34: MASK-TOP
User.35: MASK-BOT
User.36: FAB
User.37: PAST-TOP
User.38: PAST-BOT
User.39: GND | 2
User.40: VCC | 4
User.41: IN1 | 3
User.42: IN2 | 6
User.43: IN3 | 5
User.44: IN4 | 7
User.45: FIGURE | SIZE | 10.0 | 22.0 | 28.0 | 30.0 | 36.0 | 39.0 | 43.0 | 44.0 | 57.0 | 63.0 | 52.0 | 95.0 | 99.0 | 126.0 | 132.0 | 158.0 | 205.0 | 315.0 | 244.0x205.0 | DRILL CHART: TOP to BOTTOM | ALL UNITS ARE IN MILS | TOLERANCE | +3.0/-3.0 | +2.0/-2.0 | +4.0/-4.0 | PLATED | NON-PLATED | QTY | 1641 | 260 | 96 | 328 | 528 | 72 | 32 | 11 | 384 | 20 | 4 | 10 | 24 | 8 | 12 | 1 | PANEL | GND1 | VCC1 | 5 | 7 | DETAIL A
